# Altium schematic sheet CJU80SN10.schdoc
size 127 x 101 mm
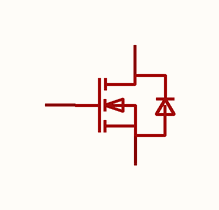
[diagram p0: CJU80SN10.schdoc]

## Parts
Q?  cju80sn10  [TO-252-2_L6.6-W6.1-P4.57-LS9.9-BR-CW]  (value not drawn)

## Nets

Not connected (* = marked no-connect by the designer): Q? 1(G) 2(D) 3(S)

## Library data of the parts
Q? = cju80sn10: 数量:1个N沟道;漏源电压(Vdss):100V;连续漏极电流(Id):80A;导通电阻(RDS(on)):10.5mΩ@4.5V;耗散功率(Pd):125W;阈值电压(Vgs(th)):2.5V;; Manufacturer: CJ(江苏长电/长晶); AddInBom: yes; ModelId: ce57f84d66384067af8a68020b6de06d; ModelName: TO-252-2L-3P_L6.6-W6.1-H2.3-LS10.1-P4.6; ModelTransform: 259.842,390.52442,0,90,0,0,-39.39,0,0; Number: 1个N沟道; Drain to Source Voltage: 100V; Current - Continuous Drain(Id): 80A; Pd - Power Dissipation: 125W; Gate Threshold Voltage (Vgs(th)): 2.5V; Gate Charge(Qg): 100nC@10V; Input Capacitance(Ciss): 3.15nF; Reverse Transfer Capacitance (Crss@Vds): 8pF; Type: N沟道; Output Capacitance(Coss): 420pF; Vgs: ±20V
